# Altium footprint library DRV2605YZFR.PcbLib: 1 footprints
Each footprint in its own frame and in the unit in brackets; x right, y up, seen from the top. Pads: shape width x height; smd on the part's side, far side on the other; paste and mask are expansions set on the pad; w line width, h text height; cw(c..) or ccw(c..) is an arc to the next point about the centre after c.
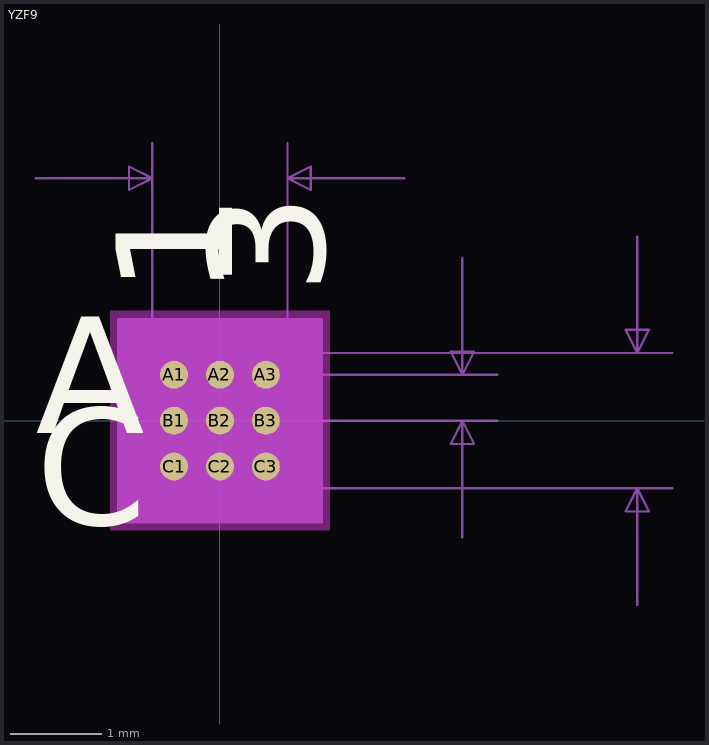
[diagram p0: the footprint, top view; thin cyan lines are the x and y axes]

## YZF9 [mil]
pads (9):
  round 12 smd: A1(-19.68,19.68) A2(0,19.68) A3(19.68,19.68) B1(-19.68,0) B2(0,0) B3(19.68,0) C1(-19.68,-19.68) C2(0,-19.68) C3(19.68,-19.68)
Top Overlay:
  text "A" at -79,-5.32 h50
  text "C" at -79,-44.69 h50
  text "1" at 5.32,54 h50
  text "3" at 44.69,54 h50
Bottom Overlay:
  text "A" at -54,-5.32 h50
  text "C" at -54,-44.69 h50
  text "1" at -44.69,54 h50
  text "3" at -5.32,54 h50
Keep-Out Layer:
  region: -47.03,-47.03 -47.03,47.03 47.03,47.03 47.03,-47.03
Mechanical 5:
  region: 44,-44 -44,-44 -44,44 44,44
Mechanical 7:
  lines w1: -79,104 -29,104 ; -29,0 -29,119 ; 0,-29 194,-29 ; 0,29 194,29 ; 19.68,0 119,0 ; 19.68,19.68 119,19.68 ; 29,0 29,119 ; 79,104 29,104 ; 104,-50 104,0 ; 104,69.69 104,19.68 ; 179,-79 179,-29 ; 179,79 179,29 ; -29,104 -39,109 -39,99 -29,104 ; 29,104 39,109 39,99 29,104 ; 104,0 99,-10 109,-10 104,0 ; 104,19.68 99,29.68 109,29.68 104,19.68 ; 179,-29 174,-39 184,-39 179,-29 ; 179,29 174,39 184,39 179,29
  text "Default Padstyle: EX12Y12D0T" at -350,-229 h50
  text "1.968504E-02in/0.5mm" at 124,-2.66 h25
  text "0.058in/1.473mm" at -93.75,124 h25
  text "0.058in/1.473mm" at 199,-12.5 h25
Mechanical 13:
  lines w1: -29,19.16 -19.16,29 ; -29,-29 29,-29 29,29 -29,29 -29,-29
  text "A" at -79,-5.32 h50
  text "C" at -79,-44.69 h50
  text "1" at 5.32,54 h50
  text "3" at 44.69,54 h50
Mechanical 15:
  region: 39,-39 -39,-39 -39,39 39,39
  lines w6: -39,-39 -39,39 39,39 39,-39 -39,-39
3D body: height 10, standoff 0, extent 0,0 10,10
